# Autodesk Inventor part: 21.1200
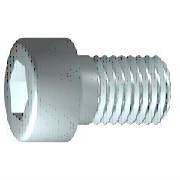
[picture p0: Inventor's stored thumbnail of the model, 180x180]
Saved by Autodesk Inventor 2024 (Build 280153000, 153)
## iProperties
Created: 2006-02
Part Number: 21.1200
Material: Steel, Mild
Description: M8 x 16 SHCS
Document SubType Name: Modeling
Standard: DIN 7984
Designer: Andy Moles
Standards Organization: DIN
Language: en-US
Size Designation: M8 x 16
Categories: <MemberInstance><Categories><Category DisplayName="Fasteners" InternalName="e4da775c-781d-43d5-af7c-5136215cf5a6" Mnemonic="FSTN"><Category DisplayName="Bolts"
Density: 7.85 g/cm^3
Mass: 10.6691 g
Surface Area: 9.17139 cm^2
Volume: 1.35912 cm^3
Vendor: S
Appearance: Zinc
Author: Andy Moles
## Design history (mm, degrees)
body "Solid1"
workplane "Work Plane1"
revolve "Body" stored, may be unused: angle "d10" = 90 deg
sketch "Sketch2"
  geometry: L1 (0, -9.1)-(0, 9.1) reference; L2 (-9.1, 0)-(9.1, 0) reference; L3 (2.887, 0)-(1.443, -2.5); L4 (1.443, -2.5)-(-1.443, -2.5); L5 (-1.443, -2.5)-(-2.887, 0); L6 (-2.887, 0)-(-1.443, 2.5); L7 (-1.443, 2.5)-(1.443, 2.5); L8 (1.443, 2.5)-(2.887, 0); 2 further points
  constraints: 12 end point, 1 coincident, 1 horizontal alignment, 1 point on line, 12 other
extrude "Slot" join sketch "Sketch2" stored distance "d11" = 10; taper "d12" = 0 deg
fillet "Fillet1" dims "d17" = 0.8 (= RR)
feature "Thread" dims "d13" = 16, "d14" = 0
chamfer "Chamfer1" distance "d15" = 0.76681 (= -0.5 x SPD + 0.5 x GD); stored, may be unused: second distance "d16" = 0.76681 (= GUL), angle "d27" = 45 deg
sketch "Sketch1"
  geometry: L1 (0.467, 0)-(16, 0); L2 (16, 0)-(16, 4); L3 (16, 4)-(3.75, 4); L4 (3.75, 4)-(2.983, 4); L5 (2.983, 4)-(0, 4); L6 (0, 4)-(0, 6.5); L7 (0, 6.5)-(-5, 6.5); L8 (-5, 6.5)-(-5, 2.887); L9 (-5, 2.887)-(-1.2, 2.887); L10 (-1.2, 2.887)-(0.467, 0); L11 (-9.2, 0)-(20.2, 0) reference; L12 (0, -1.3)-(0, 7.8) reference; L13 (3.75, 4)-(0, 4)
  constraints: 22 end point, 6 parallel, 2 collinear, 2 perpendicular, 1 horizontal, 1 point on line
  dimensions: "d1" = 12.25 distance from line of L3.end L2 (= GEL); "d2" = 0.76691 distance of L4.end L3.end (computed from GAL); "d3" = 5 distance between parallel lines of L8 L6 (= KOH); "d4" = 3.8 distance of L8.end L9.end (= INTI); "d5" = 60 deg angle of L10 L1; "d6" = 8 diameter of L3 L1 (= GD); "d7" = 8 diameter of L5 L1 (= BDM); "d8" = 5.7735 diameter of L9 L1 (= 1.1547 x SW); "d9" = 13 diameter of L7 L1 (= KOD); "d26" = 16 distance between parallel lines of L12 L2 (= NLG)
other parameters: "GD" = 8 (= NND) [user parameter; used in 2 equation terms], "NLG" = 16 [user parameter; used in 1 equation term], "GEL" = 12.25 [user parameter; used in 1 equation term], "KOD" = 13 [user parameter; used in 1 equation term], "KOH" = 5 [user parameter; used in 1 equation term], "INTI" = 3.8 [user parameter; used in 1 equation term], "GAL" = 0.76681 (= 0.61345 x PTC) [user parameter; used in 1 equation term], "GUL" = 0.76681 (= 0.61345 x PTC) [user parameter; used in 1 equation term], "BDM" = 8 (= NND) [user parameter; used in 1 equation term], "SW" = 5 [user parameter; used in 2 equation terms], "RR" = 0.8 [user parameter; used in 1 equation term], "SPD" = 6.46637 (= NND - 1.2269 x PTC) [user parameter; used in 1 equation term], "d19" = 0, "d28" = 0, "d29" = 0, "TOA" = 30 deg [user parameter], "GD1" = 6.46637 (= THREADDIA - 1.2269 x PTC) [user parameter], "THREADDIA" = 8 [user parameter; used in 1 equation term], "FAWI" = 45 deg [user parameter], "ANG" = 120 deg [user parameter], "TPU" = 8 (computed from PTC) [user parameter], "PTC" = 1.25 [user parameter; used in 5 equation terms], "NND" = 8 [user parameter; used in 3 equation terms], "E0" = 5.775 (= 1.155 x SW) [user parameter]
